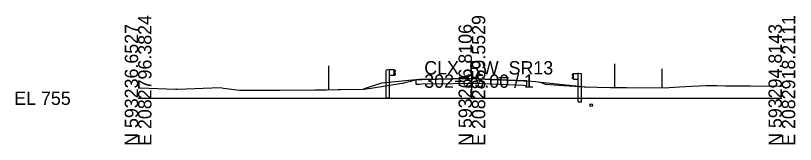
# Model space of a CAD drawing. Extents: x -26 to 2138, y -10 to 4518.
# Drawn here: x -25.7 to 137.8, y 1990.3 to 2017.4 of the extents above; entities that cross this region are included whole.
import ezdxf

# ---------------------------------------------------------------- set-up
doc = ezdxf.new("R2010")
doc.units = 0
for name, color, linetype in [('GK_Cells', 7, 'Continuous'), ('MD_X_Asphalt_Pavement', 7, 'Continuous'), ('RD_P_Cells', 7, 'Continuous'), ('RW_P_Esmt_SH', 7, 'Continuous'), ('RW_X_Esmt_SH', 7, 'Continuous'), ('UT_X_Water', 7, 'Continuous'), ('XS_P_Finished_Grade', 7, 'Continuous'), ('XS_X_Ground_Line', 7, 'Continuous')]:
    doc.layers.add(name, color=color, linetype=linetype)

msp = doc.modelspace()

# ---------------------------------------------------------------- linework, layer by layer
at = {"layer": 'GK_Cells'}
for p, q in [((70, 2000), (70, 2005)), ((0, 2000), (70, 2000)), ((70, 2000), (135, 2000))]:
    msp.add_line(p, q, dxfattribs=at)
at = {"layer": 'MD_X_Asphalt_Pavement'}
msp.add_lwpolyline([(58.98, 2003.94), (58.27, 2003.9), (58.27, 2002.94), (58.98, 2002.98), (59.48, 2003.01), (66.05, 2003.13), (70.01, 2003.2), (74.13, 2003.01), (80.83, 2002.75), (81.23, 2002.72), (81.52, 2002.69), (81.52, 2003.65), (81.23, 2003.68), (80.83, 2003.7), (74.13, 2003.97), (70.01, 2004.16), (66.05, 2004.09), (59.48, 2003.96), (58.98, 2003.94)], dxfattribs=at)
at = {"layer": 'RD_P_Cells'}
for p, q in [((52.1, 2005.93), (52.05, 2005.91)), ((52.05, 2000.02), (52.05, 2005.91)), ((52.64, 2006.02), (52.1, 2005.93)), ((52.72, 2005.97), (52.64, 2006.02)), ((53.72, 2005.97), (52.72, 2005.97)), ((52.72, 2000.02), (52.72, 2005.97)), ((53.72, 2004.79), (53.72, 2005.97)), ((53.81, 2005.88), (53.72, 2005.89)), ((53.73, 2005.38), (53.73, 2005.43)), ((53.73, 2005.33), (53.73, 2005.38)), ((53.76, 2005.49), (53.97, 2005.63)), ((53.97, 2005.13), (53.76, 2005.27)), ((53.97, 2005.76), (53.81, 2005.88)), ((53.81, 2004.89), (53.97, 2005)), ((91.03, 2005.01), (91.19, 2005.13)), ((91.19, 2005.13), (91.28, 2005.14)), ((91.28, 2004.04), (91.28, 2005.22)), ((91.28, 2005.22), (92.28, 2005.22)), ((92.28, 2005.22), (92.36, 2005.27)), ((92.28, 1999.27), (92.28, 2005.22)), ((92.36, 2005.27), (92.9, 2005.18)), ((92.9, 2005.18), (92.95, 2005.16)), ((92.95, 1999.27), (92.95, 2005.16)), ((53.72, 2004.79), (52.72, 2004.79)), ((53.72, 2004.87), (53.81, 2004.89)), ((91.24, 2004.74), (91.03, 2004.88)), ((91.03, 2004.38), (91.24, 2004.52)), ((91.19, 2004.14), (91.03, 2004.25)), ((91.28, 2004.12), (91.19, 2004.14)), ((91.27, 2004.63), (91.27, 2004.68)), ((91.27, 2004.58), (91.27, 2004.63)), ((91.28, 2004.04), (92.28, 2004.04)), ((52.72, 2000.02), (52.05, 2000.02)), ((92.28, 1999.27), (92.95, 1999.27))]:
    msp.add_line(p, q, dxfattribs=at)
for points in [[(53.74, 2005.44), (53.74, 2005.32), (53.73, 2005.32), (53.73, 2005.44)], [(53.74, 2005.41), (53.74, 2005.35), (53.76, 2005.35), (53.76, 2005.41)], [(91.26, 2004.66), (91.26, 2004.6), (91.24, 2004.6), (91.24, 2004.66)], [(91.26, 2004.69), (91.26, 2004.57), (91.27, 2004.57), (91.27, 2004.69)]]:
    msp.add_lwpolyline(points, close=True, dxfattribs=at)
for centre, start, end in [((53.81, 2005.43), 124.962, 180), ((53.81, 2005.33), 180, 235.038), ((53.92, 2005.7), 304.962, 54.7677), ((53.92, 2005.06), 304.962, 54.7677), ((91.08, 2004.95), 125.2323, 235.038), ((91.08, 2004.31), 125.2323, 235.038), ((91.19, 2004.68), 0, 55.038), ((91.19, 2004.58), 304.962, 0)]:
    msp.add_arc(centre, 0.0781, start, end, dxfattribs=at)
at = {"layer": 'RW_P_Esmt_SH'}
msp.add_line((109.92, 2002.2), (109.92, 2006.2), dxfattribs=at)
at = {"layer": 'RW_X_Esmt_SH'}
for p, q in [((40, 2001.81), (40, 2006.81)), ((100, 2002.27), (100, 2007.27))]:
    msp.add_line(p, q, dxfattribs=at)
at = {"layer": 'UT_X_Water'}
msp.add_circle((95, 1998.56), 0.3, dxfattribs=at)
at = {"layer": 'XS_P_Finished_Grade'}
for p, q in [((58.27, 2003.9), (51.05, 2003.18)), ((84.41, 2003.38), (94.54, 2002.37)), ((51.05, 2003.18), (47.17, 2001.89))]:
    msp.add_line(p, q, dxfattribs=at)
at = {"layer": 'XS_X_Ground_Line'}
msp.add_lwpolyline([(0, 2002.19), (0.44, 2002.18), (7.85, 2001.93), (7.88, 2001.93), (8.23, 2001.94), (17.31, 2002.25), (17.93, 2002.16), (21.27, 2001.69), (29.65, 2001.74), (37.06, 2001.79), (38.19, 2001.8), (39.44, 2001.81), (41.93, 2001.83), (42.36, 2001.83), (42.47, 2001.83), (47.27, 2001.89), (48.87, 2002.13), (54.92, 2003.08), (55.44, 2003.16), (55.57, 2003.19), (55.71, 2003.22), (58.27, 2003.9), (58.98, 2003.94), (59.48, 2003.96), (66.05, 2004.09), (70.01, 2004.16), (74.13, 2003.97), (80.83, 2003.7), (81.23, 2003.68), (81.52, 2003.65), (83.44, 2003.5), (84.41, 2003.38), (85.37, 2003), (88.2, 2002.76), (93.54, 2002.39), (98.99, 2002.27), (99.13, 2002.27), (102.4, 2002.25), (110.29, 2002.2), (113.51, 2002.38), (116.11, 2002.53), (119.13, 2002.67), (121.36, 2002.66), (123.23, 2002.64), (128.34, 2002.62), (130.74, 2002.52), (135, 2002.62)], dxfattribs=at)

# ---------------------------------------------------------------- texts
msp.add_text('-', height=0.0001).set_placement((0, 2000))
at = {"layer": 'GK_Cells'}
for s, p in [('E 2082796.3824', (2.8, 1990)), ('E 2082859.5529', (72.8, 1990)), ('E 2082918.2111', (137.8, 1990)), ('N 593236.6527', (0, 1990)), ('N 593266.8106', (70, 1990)), ('N 593294.8143', (135, 1990))]:
    msp.add_text(s, height=2.8, rotation=90, dxfattribs=at).set_placement(p)
for s, p in [('CLX_RW_SR13', (60, 2005)), ('302+25.00 / 1', (60, 2002.2)), ('EL 755', (-26, 1998.6))]:
    msp.add_text(s, height=2.8, dxfattribs=at).set_placement(p)

doc.saveas('drawing.dxf')
